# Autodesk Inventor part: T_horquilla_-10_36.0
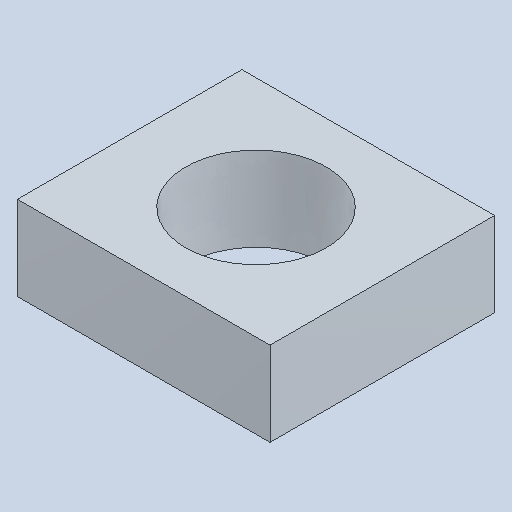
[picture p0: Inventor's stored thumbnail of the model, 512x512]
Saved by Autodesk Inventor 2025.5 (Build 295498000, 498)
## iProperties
Created: 2026-10
Part Number: T_horquilla_-10_36.0
Material: Genérico
Document SubType Name: Modeling
Designer: Luis M
Density: 1 g/cm^3
Appearance: Valor por defecto
Author: Luis M
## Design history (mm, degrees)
feature "Base1"
node "Sólido1"
